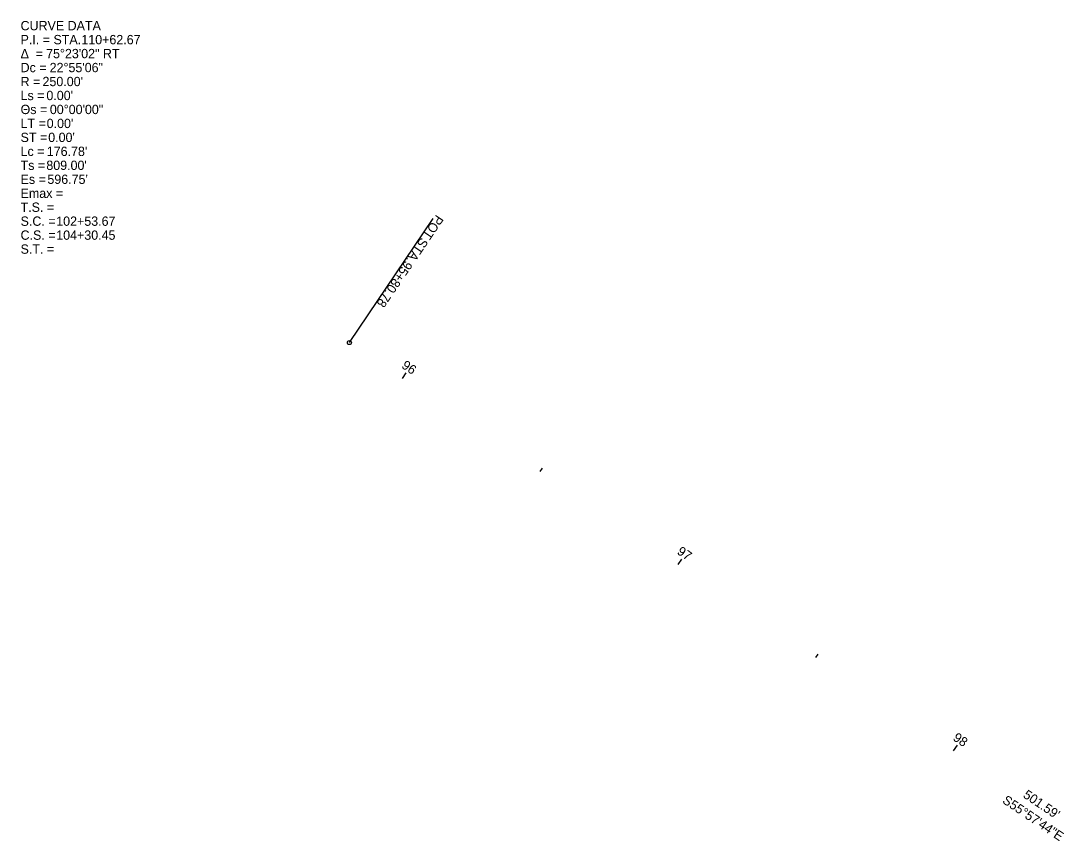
# Model space of a CAD drawing. Extents: x 1600023 to 1602131, y 285824 to 287284.
# Drawn here: x 1600258.1 to 1600571.8, y 287037.4 to 287284.1 of the extents above; entities that cross this region are included whole.
import ezdxf

# ---------------------------------------------------------------- set-up
doc = ezdxf.new("R2010")
doc.units = 0
for name, color, linetype in [('PM_P_CL_Double_Solid', 7, 'Continuous'), ('PM_P_Dotted_Line', 7, 'Continuous'), ('PM_P_Edge_Line', 7, 'Continuous'), ('PM_P_Transverse_Line', 7, 'Continuous'), ('PM_P_Yield_Line', 7, 'Continuous')]:
    doc.layers.add(name, color=color, linetype=linetype)

msp = doc.modelspace()

# ---------------------------------------------------------------- linework, layer by layer
at = {"layer": 'PM_P_CL_Double_Solid'}
msp.add_line((1600356.88, 287187.32), (1600382.06, 287224.61), dxfattribs=at)
msp.add_circle((1600356.88, 287187.32), 0.6, dxfattribs=at)
at = {"layer": 'PM_P_Transverse_Line'}
for p, q in [((1600372.8, 287176.56), (1600373.92, 287178.22)), ((1600414.24, 287148.57), (1600414.91, 287149.57)), ((1600455.67, 287120.59), (1600456.79, 287122.24)), ((1600497.1, 287092.6), (1600497.78, 287093.59)), ((1600538.54, 287064.61), (1600539.66, 287066.27))]:
    msp.add_line(p, q, dxfattribs=at)

# ---------------------------------------------------------------- texts
at = {"layer": 'PM_P_CL_Double_Solid'}
for s, p in [('POT', (1600383.03, 287225.97)), (' STA. ', (1600379, 287220)), ('95+80.78', (1600373.71, 287212.17))]:
    msp.add_text(s, height=2.8, rotation=235.9623, dxfattribs=at).set_placement(p)
at = {"layer": 'PM_P_Dotted_Line'}
msp.add_text("501.59'", height=2.8, rotation=325.9623, dxfattribs=at).set_placement((1600559.19, 287050.71))
at = {"layer": 'PM_P_Edge_Line'}
msp.add_text('S55°57\'44"E', height=2.8, rotation=325.9623, dxfattribs=at).set_placement((1600552.95, 287049.08))
at = {"layer": 'PM_P_Transverse_Line'}
for s, p in [('96', (1600372.35, 287179.89)), ('97', (1600455.16, 287123.94)), ('98', (1600538.1, 287067.93))]:
    msp.add_text(s, height=2.8, rotation=325.9623, dxfattribs=at).set_placement(p)
at = {"layer": 'PM_P_Yield_Line'}
for s, p in [('CURVE DATA', (1600258.03, 287281.25)), ('P.I. = STA. ', (1600258.03, 287277.05)), ('110+62.67', (1600276.3, 287277.05)), ('Δ  = ', (1600258.03, 287272.85)), ('75°23\'02" RT', (1600265.71, 287272.85)), ('Dc = ', (1600258.03, 287268.65)), ('22°55\'06"', (1600266.77, 287268.65)), ('R = ', (1600258.03, 287264.45)), ("250.00'", (1600264.62, 287264.45)), ('Ls = ', (1600258.03, 287260.25)), ("0.00'", (1600265.79, 287260.25)), ('Θs = ', (1600258.03, 287256.05)), ('00°00\'00"', (1600266.83, 287256.05)), ('LT = ', (1600258.03, 287251.85)), ("0.00'", (1600265.88, 287251.85)), ('ST = ', (1600258.03, 287247.65)), ("0.00'", (1600266.34, 287247.65)), ('Lc = ', (1600258.03, 287243.45)), ("176.78'", (1600265.91, 287243.45)), ('Ts = ', (1600258.03, 287239.25)), ("809.00'", (1600265.77, 287239.25)), ('Es = ', (1600258.03, 287235.05)), ("596.75'", (1600266.09, 287235.05)), ('Emax = ', (1600258.03, 287230.85)), ('T.S. = ', (1600258.03, 287226.65)), ('S.C. = ', (1600258.03, 287222.45)), ('102+53.67', (1600268.75, 287222.45)), ('C.S. = ', (1600258.03, 287218.25)), ('104+30.45', (1600268.75, 287218.25)), ('S.T. = ', (1600258.03, 287214.05))]:
    msp.add_text(s, height=2.8, dxfattribs=at).set_placement(p)

doc.saveas('drawing.dxf')
